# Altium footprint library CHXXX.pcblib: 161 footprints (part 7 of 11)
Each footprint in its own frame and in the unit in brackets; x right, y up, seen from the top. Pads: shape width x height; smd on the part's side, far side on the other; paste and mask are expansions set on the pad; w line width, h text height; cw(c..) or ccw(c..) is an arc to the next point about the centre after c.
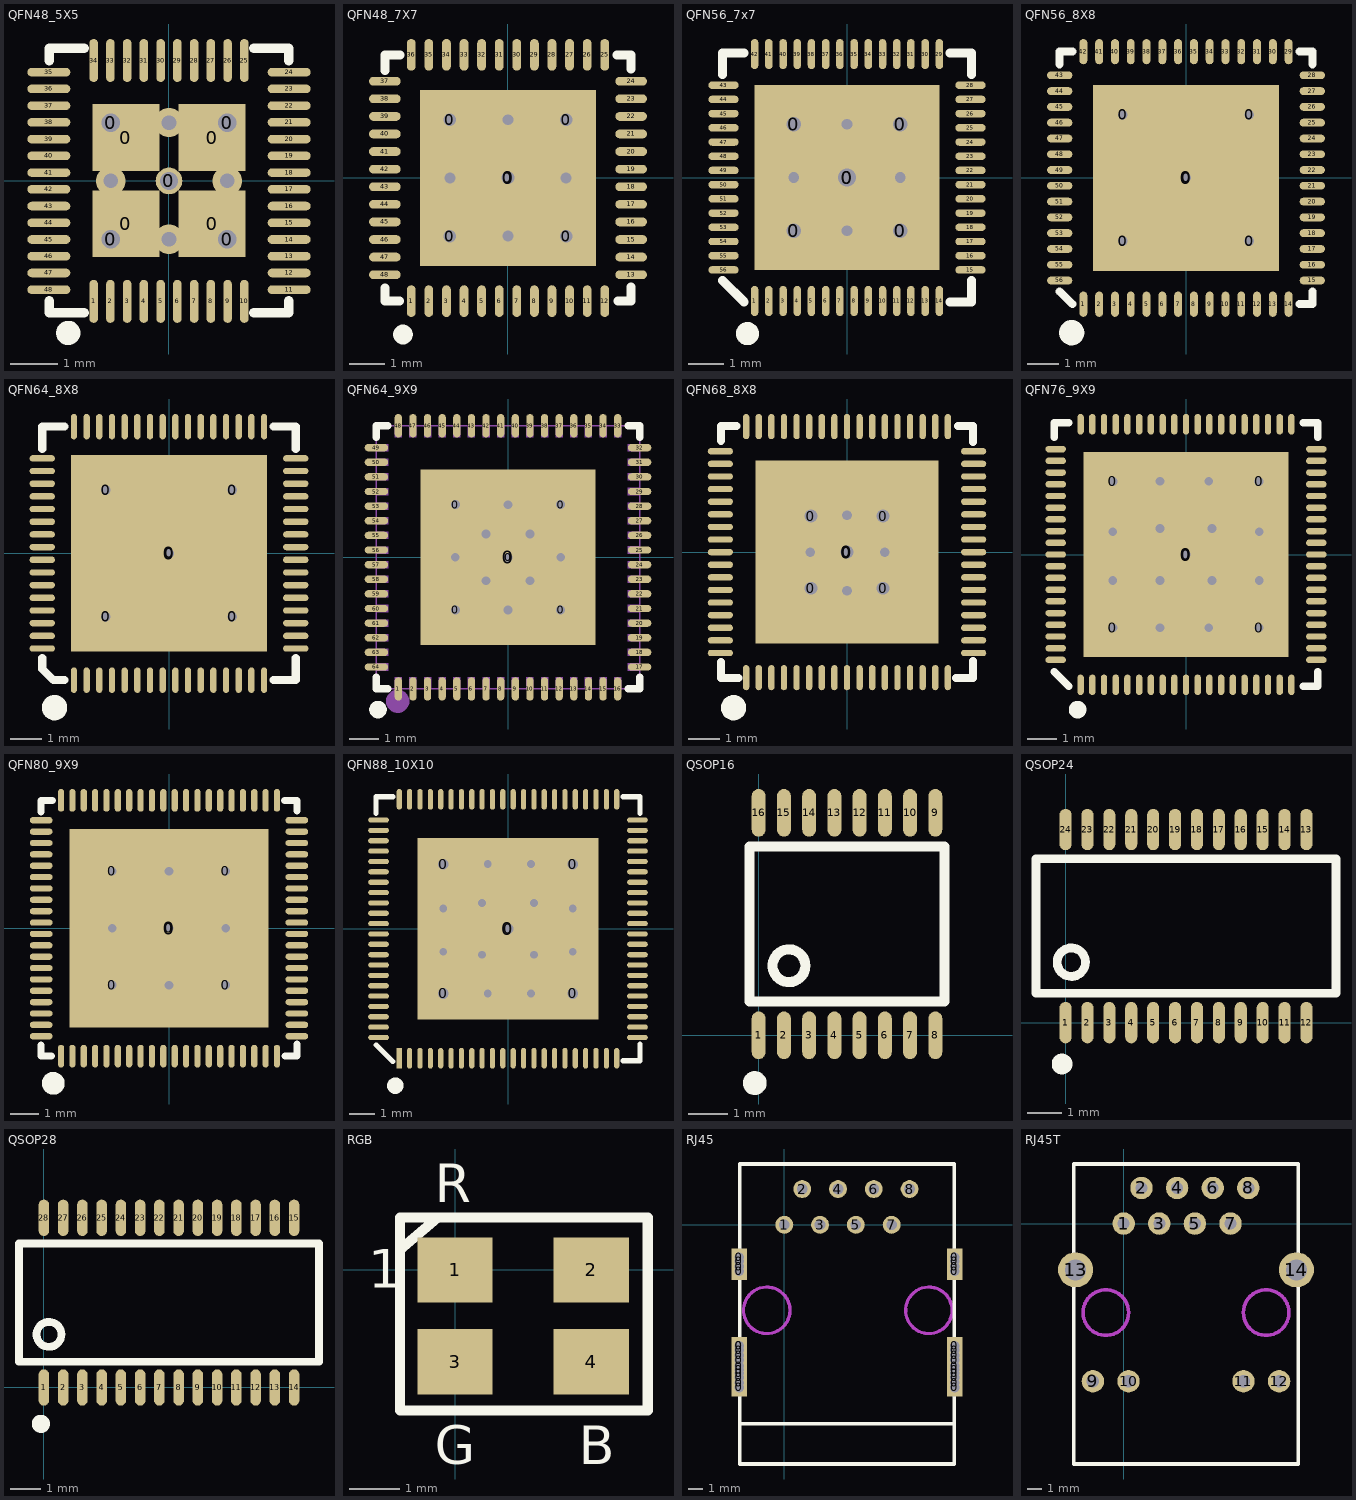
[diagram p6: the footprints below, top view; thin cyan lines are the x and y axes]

## QFN48_5X5 [mm]
pads (57):
  round 0.559 hole 0.381 mask+0.102: 0(-1.219,-1.219) 0(-1.219,1.219) 0(0,0) 0(1.219,-1.219) 0(1.219,1.219)
  rect 1.397x1.397 smd mask+0: 0(-0.901,-0.895) 0(-0.901,0.908) 0(0.902,-0.895) 0(0.902,0.908)
  oval 0.18x0.9 smd mask+0.051: 1(-1.575,-2.519) 2(-1.225,-2.519) 3(-0.875,-2.519) 4(-0.525,-2.519) 5(-0.175,-2.519) 6(0.175,-2.519) 7(0.525,-2.519) 8(0.875,-2.519) 9(1.225,-2.519) 10(1.575,-2.519) 25(1.575,2.519) 26(1.225,2.519) 27(0.875,2.519) 28(0.525,2.519) 29(0.175,2.519) 30(-0.175,2.519) 31(-0.525,2.519) 32(-0.875,2.519) 33(-1.225,2.519) 34(-1.575,2.519)
  oval 0.9x0.18 smd mask+0.051: 11(2.514,-2.275) 12(2.514,-1.925) 13(2.514,-1.575) 14(2.514,-1.225) 15(2.514,-0.875) 16(2.514,-0.525) 17(2.514,-0.175) 18(2.514,0.175) 19(2.514,0.525) 20(2.514,0.875) 21(2.514,1.225) 22(2.514,1.575) 23(2.514,1.925) 24(2.514,2.275) 35(-2.514,2.275) 36(-2.514,1.925) 37(-2.514,1.575) 38(-2.514,1.225) 39(-2.514,0.875) 40(-2.514,0.525) 41(-2.514,0.175) 42(-2.514,-0.175) 43(-2.514,-0.525) 44(-2.514,-0.875) 45(-2.514,-1.225) 46(-2.514,-1.575) 47(-2.514,-1.925) 48(-2.514,-2.275)
via 1.219,0 diameter 0.61 hole 0.305
via 0,-1.219 diameter 0.61 hole 0.305
via -1.219,0 diameter 0.61 hole 0.305
via 0,1.219 diameter 0.61 hole 0.305
TopOverlay:
  circle w0.254: c-2.108,-3.179 r0.127
  lines w0.2: -2.509,-2.506 -2.509,-2.76 -1.778,-2.76 ; -2.509,2.519 -2.509,2.772 -1.778,2.772 ; 1.778,-2.76 2.509,-2.76 2.509,-2.506 ; 1.778,2.772 2.509,2.772 2.509,2.519

## QFN48_7X7 [mm]
pads (54):
  round 0.559 hole 0.356 mask+0.102: 0(-1.651,-1.651) 0(-1.651,1.651) 0(0,0) 0(1.651,-1.651) 0(1.651,1.651)
  rect 5x5 smd mask+0.051: 0(0,0)
  oval 0.25x0.9 smd mask+0.051: 1(-2.75,-3.5) 2(-2.25,-3.5) 3(-1.75,-3.5) 4(-1.25,-3.5) 5(-0.75,-3.5) 6(-0.25,-3.5) 7(0.25,-3.5) 8(0.75,-3.5) 9(1.25,-3.5) 10(1.75,-3.5) 11(2.25,-3.5) 12(2.75,-3.5) 25(2.75,3.5) 26(2.25,3.5) 27(1.75,3.5) 28(1.25,3.5) 29(0.75,3.5) 30(0.25,3.5) 31(-0.25,3.5) 32(-0.75,3.5) 33(-1.25,3.5) 34(-1.75,3.5) 35(-2.25,3.5) 36(-2.75,3.5)
  oval 0.9x0.25 smd mask+0.051: 13(3.5,-2.75) 14(3.5,-2.25) 15(3.5,-1.75) 16(3.5,-1.25) 17(3.5,-0.75) 18(3.5,-0.25) 19(3.5,0.25) 20(3.5,0.75) 21(3.5,1.25) 22(3.5,1.75) 23(3.5,2.25) 24(3.5,2.75) 37(-3.5,2.75) 38(-3.5,2.25) 39(-3.5,1.75) 40(-3.5,1.25) 41(-3.5,0.75) 42(-3.5,0.25) 43(-3.5,-0.25) 44(-3.5,-0.75) 45(-3.5,-1.25) 46(-3.5,-1.75) 47(-3.5,-2.25) 48(-3.5,-2.75)
via -1.651,0 diameter 0.61 hole 0.305
via 0,1.651 diameter 0.61 hole 0.305
via 1.651,0 diameter 0.61 hole 0.305
via 0,-1.651 diameter 0.61 hole 0.305
TopOverlay:
  circle w0.305: c-2.986,-4.451 r0.127
  lines w0.254: -3.5,-3.128 -3.5,-3.5 -3.082,-3.5 ; -3.5,3.057 -3.5,3.5 -3.066,3.5 ; 3.099,3.5 3.5,3.5 3.5,3.096 ; 3.126,-3.5 3.5,-3.5 3.5,-3.104

## QFN56_7x7 [mm]
pads (62):
  round 0.762 hole 0.406: 0(-1.5,-1.5) 0(-1.5,1.5) 0(1.5,-1.5) 0(1.5,1.5)
  rect 5.2x5.2 smd mask+0.05: 0(0,0)
  round 0.889 hole 0.508: 0(0,0)
  oval 0.21x0.85 smd mask+0.051: 1(-2.6,-3.475) 2(-2.2,-3.475) 3(-1.8,-3.475) 4(-1.4,-3.475) 5(-1,-3.475) 6(-0.6,-3.475) 7(-0.2,-3.475) 8(0.2,-3.475) 9(0.6,-3.475) 10(1,-3.475) 11(1.4,-3.475) 12(1.8,-3.475) 13(2.2,-3.475) 14(2.6,-3.475) 29(2.6,3.475) 30(2.2,3.475) 31(1.8,3.475) 32(1.4,3.475) 33(1,3.475) 34(0.6,3.475) 35(0.2,3.475) 36(-0.2,3.475) 37(-0.6,3.475) 38(-1,3.475) 39(-1.4,3.475) 40(-1.8,3.475) 41(-2.2,3.475) 42(-2.6,3.475)
  oval 0.85x0.21 smd mask+0.051: 15(3.475,-2.6) 16(3.475,-2.2) 17(3.475,-1.8) 18(3.475,-1.4) 19(3.475,-1) 20(3.475,-0.6) 21(3.475,-0.2) 22(3.475,0.2) 23(3.475,0.6) 24(3.475,1) 25(3.475,1.4) 26(3.475,1.8) 27(3.475,2.2) 28(3.475,2.6) 43(-3.475,2.6) 44(-3.475,2.2) 45(-3.475,1.8) 46(-3.475,1.4) 47(-3.475,1) 48(-3.475,0.6) 49(-3.475,0.2) 50(-3.475,-0.2) 51(-3.475,-0.6) 52(-3.475,-1) 53(-3.475,-1.4) 54(-3.475,-1.8) 55(-3.475,-2.2) 56(-3.475,-2.6)
via -1.5,0 diameter 0.6 hole 0.3
via 0,1.5 diameter 0.6 hole 0.3
via 1.5,0 diameter 0.6 hole 0.3
via 0,-1.5 diameter 0.6 hole 0.3
TopOverlay:
  circle w0.35: c-2.803,-4.395 r0.15
  lines w0.254: -3.5,-2.899 -2.899,-3.5 ; -3.5,2.899 -3.5,3.5 -2.899,3.5 ; 2.899,-3.5 3.5,-3.5 3.5,-2.899 ; 2.899,3.5 3.5,3.5 3.5,2.899

## QFN56_8X8 [mm]
pads (62):
  round 0.61 hole 0.305 mask+0.051: 0(-2,-2) 0(-2,2) 0(0,0) 0(2,-2) 0(2,2)
  rect 5.9x5.9 smd mask+0.051: 0(0,0)
  oval 0.25x0.8 smd mask+0.051: 1(-3.25,-4) 2(-2.75,-4) 3(-2.25,-4) 4(-1.75,-4) 5(-1.25,-4) 6(-0.75,-4) 7(-0.25,-4) 8(0.25,-4) 9(0.75,-4) 10(1.25,-4) 11(1.75,-4) 12(2.25,-4) 13(2.75,-4) 14(3.25,-4) 29(3.25,4) 30(2.75,4) 31(2.25,4) 32(1.75,4) 33(1.25,4) 34(0.75,4) 35(0.25,4) 36(-0.25,4) 37(-0.75,4) 38(-1.25,4) 39(-1.75,4) 40(-2.25,4) 41(-2.75,4) 42(-3.25,4)
  oval 0.8x0.25 smd mask+0.051: 15(4,-3.25) 16(4,-2.75) 17(4,-2.25) 18(4,-1.75) 19(4,-1.25) 20(4,-0.75) 21(4,-0.25) 22(4,0.25) 23(4,0.75) 24(4,1.25) 25(4,1.75) 26(4,2.25) 27(4,2.75) 28(4,3.25) 43(-4,3.25) 44(-4,2.75) 45(-4,2.25) 46(-4,1.75) 47(-4,1.25) 48(-4,0.75) 49(-4,0.25) 50(-4,-0.25) 51(-4,-0.75) 52(-4,-1.25) 53(-4,-1.75) 54(-4,-2.25) 55(-4,-2.75) 56(-4,-3.25)
TopOverlay:
  circle w0.4: c-3.621,-4.903 r0.2
  lines w0.254: -4,-3.6 -3.6,-4 ; -4,3.6 -4,4 -3.6,4 ; 3.6,-4 4,-4 4,-3.6 ; 3.6,4 4,4 4,3.6

## QFN64_8X8 [mm]
pads (70):
  round 0.61 hole 0.305 mask+0.051: 0(-2,-2) 0(-2,2) 0(0,0) 0(2,-2) 0(2,2)
  rect 6.2x6.2 smd mask+0.051: 0(0,0)
  oval 0.2x0.8 smd mask+0.051: 1(-3,-4) 2(-2.6,-4) 3(-2.2,-4) 4(-1.8,-4) 5(-1.4,-4) 6(-1,-4) 7(-0.6,-4) 8(-0.2,-4) 9(0.2,-4) 10(0.6,-4) 11(1,-4) 12(1.4,-4) 13(1.8,-4) 14(2.2,-4) 15(2.6,-4) 16(3,-4) 33(3,4) 34(2.6,4) 35(2.2,4) 36(1.8,4) 37(1.4,4) 38(1,4) 39(0.6,4) 40(0.2,4) 41(-0.2,4) 42(-0.6,4) 43(-1,4) 44(-1.4,4) 45(-1.8,4) 46(-2.2,4) 47(-2.6,4) 48(-3,4)
  oval 0.8x0.2 smd mask+0.051: 17(4,-3) 18(4,-2.6) 19(4,-2.2) 20(4,-1.8) 21(4,-1.4) 22(4,-1) 23(4,-0.6) 24(4,-0.2) 25(4,0.2) 26(4,0.6) 27(4,1) 28(4,1.4) 29(4,1.8) 30(4,2.2) 31(4,2.6) 32(4,3) 49(-4,3) 50(-4,2.6) 51(-4,2.2) 52(-4,1.8) 53(-4,1.4) 54(-4,1) 55(-4,0.6) 56(-4,0.2) 57(-4,-0.2) 58(-4,-0.6) 59(-4,-1) 60(-4,-1.4) 61(-4,-1.8) 62(-4,-2.2) 63(-4,-2.6) 64(-4,-3)
TopOverlay:
  circle w0.4: c-3.613,-4.867 r0.2
  lines w0.254: -4,-3.3 -4,-3.65 -3.65,-4 -3.3,-4 ; -4,3.3 -4,4 -3.3,4 ; 3.3,-4 4,-4 4,-3.3 ; 3.3,4 4,4 4,3.3

## QFN64_9X9 [mm]
height 9.7
pads (70):
  round 0.508 hole 0.305 mask+0.051: 0(-1.8,-1.8) 0(-1.8,1.8) 0(0,0) 0(1.8,-1.8) 0(1.8,1.8)
  rect 6x6 smd mask+0.051: 0(0,0)
  oval 0.25x0.8 smd mask+0.051: 1(-3.75,-4.5) 2(-3.25,-4.5) 3(-2.75,-4.5) 4(-2.25,-4.5) 5(-1.75,-4.5) 6(-1.25,-4.5) 7(-0.75,-4.5) 8(-0.25,-4.5) 9(0.25,-4.5) 10(0.75,-4.5) 11(1.25,-4.5) 12(1.75,-4.5) 13(2.25,-4.5) 14(2.75,-4.5) 15(3.25,-4.5) 16(3.75,-4.5) 33(3.75,4.5) 34(3.25,4.5) 35(2.75,4.5) 36(2.25,4.5) 37(1.75,4.5) 38(1.25,4.5) 39(0.75,4.5) 40(0.25,4.5) 41(-0.25,4.5) 42(-0.75,4.5) 43(-1.25,4.5) 44(-1.75,4.5) 45(-2.25,4.5) 46(-2.75,4.5) 47(-3.25,4.5) 48(-3.75,4.5)
  oval 0.8x0.25 smd mask+0.051: 17(4.5,-3.75) 18(4.5,-3.25) 19(4.5,-2.75) 20(4.5,-2.25) 21(4.5,-1.75) 22(4.5,-1.25) 23(4.5,-0.75) 24(4.5,-0.25) 25(4.5,0.25) 26(4.5,0.75) 27(4.5,1.25) 28(4.5,1.75) 29(4.5,2.25) 30(4.5,2.75) 31(4.5,3.25) 32(4.5,3.75) 49(-4.5,3.75) 50(-4.5,3.25) 51(-4.5,2.75) 52(-4.5,2.25) 53(-4.5,1.75) 54(-4.5,1.25) 55(-4.5,0.75) 56(-4.5,0.25) 57(-4.5,-0.25) 58(-4.5,-0.75) 59(-4.5,-1.25) 60(-4.5,-1.75) 61(-4.5,-2.25) 62(-4.5,-2.75) 63(-4.5,-3.25) 64(-4.5,-3.75)
via 0,-1.8 diameter 0.6 hole 0.3
via 1.8,0 diameter 0.6 hole 0.3
via 0,1.8 diameter 0.6 hole 0.3
via -1.8,0 diameter 0.6 hole 0.3
via -0.75,-0.8 diameter 0.6 hole 0.3
via 0.75,-0.8 diameter 0.6 hole 0.3
via 0.75,0.8 diameter 0.6 hole 0.3
via -0.75,0.8 diameter 0.6 hole 0.3
TopOverlay:
  lines w0.254: -4.5,-4.106 -4.5,-4.5 -4.106,-4.5 ; -4.5,4.106 -4.5,4.5 -4.106,4.5 ; 4.106,-4.5 4.5,-4.5 4.5,-4.106 ; 4.106,4.5 4.5,4.5 4.5,4.106
  lines w0.3: -4.447,-5.057 ccw(c-4.445,-5.207) -4.443,-5.057
Mechanical6:
  circle w0.4: c-3.77,-4.92 r0.2
Mechanical15:
  drawing of 69 lines, arcs and shapes, not listed

## QFN68_8X8 [mm]
pads (74):
  round 0.559 hole 0.406: 0(-1.143,-1.143) 0(-1.143,1.143) 0(0,0) 0(1.143,-1.143) 0(1.143,1.143)
  rect 5.8x5.8 smd mask+0.051: 0(0,0)
  oval 0.2x0.8 smd mask+0.051: 1(-3.2,-3.982) 2(-2.8,-3.982) 3(-2.4,-3.982) 4(-2,-3.982) 5(-1.6,-3.982) 6(-1.2,-3.982) 7(-0.8,-3.982) 8(-0.4,-3.982) 9(0,-3.982) 10(0.4,-3.982) 11(0.8,-3.982) 12(1.2,-3.982) 13(1.6,-3.982) 14(2,-3.982) 15(2.4,-3.982) 16(2.8,-3.982) 17(3.2,-3.982) 35(3.2,3.982) 36(2.8,3.982) 37(2.4,3.982) 38(2,3.982) 39(1.6,3.982) 40(1.2,3.982) 41(0.8,3.982) 42(0.4,3.982) 43(0,3.982) 44(-0.4,3.982) 45(-0.8,3.982) 46(-1.2,3.982) 47(-1.6,3.982) 48(-2,3.982) 49(-2.4,3.982) 50(-2.8,3.982) 51(-3.2,3.982)
  oval 0.8x0.2 smd mask+0.051: 18(4.018,-3.2) 19(4.018,-2.8) 20(4.018,-2.4) 21(4.018,-2) 22(4.018,-1.6) 23(4.018,-1.2) 24(4.018,-0.8) 25(4.018,-0.4) 26(4.018,0) 27(4.018,0.4) 28(4.018,0.8) 29(4.018,1.2) 30(4.018,1.6) 31(4.018,2) 32(4.018,2.4) 33(4.018,2.8) 34(4.018,3.2) 52(-4.018,3.2) 53(-4.018,2.8) 54(-4.018,2.4) 55(-4.018,2) 56(-4.018,1.6) 57(-4.018,1.2) 58(-4.018,0.8) 59(-4.018,0.4) 60(-4.018,0) 61(-4.018,-0.4) 62(-4.018,-0.8) 63(-4.018,-1.2) 64(-4.018,-1.6) 65(-4.018,-2) 66(-4.018,-2.4) 67(-4.018,-2.8) 68(-4.018,-3.2)
via 1.194,0 diameter 0.61 hole 0.305
via 0,-1.219 diameter 0.61 hole 0.305
via -1.168,0 diameter 0.61 hole 0.305
via 0,1.168 diameter 0.61 hole 0.305
TopOverlay:
  circle w0.4: c-3.599,-4.935 r0.2
  lines w0.254: -4,-3.492 -4,-4 -3.447,-4 ; -4,3.534 -4,4 -3.503,4 ; 3.459,-4 4,-4 4,-3.458 ; 3.517,4 4,4 4,3.498

## QFN76_9X9 [mm]
pads (82):
  round 0.61 hole 0.305 mask+0.051: 0(-2.5,-2.5) 0(-2.5,2.5) 0(0,0) 0(2.5,-2.5) 0(2.5,2.5)
  rect 7x7 smd mask+0.051: 0(0,0)
  oval 0.22x0.7 smd mask+0.051: 1(-3.6,-4.45) 2(-3.2,-4.45) 3(-2.8,-4.45) 4(-2.4,-4.45) 5(-2,-4.45) 6(-1.6,-4.45) 7(-1.2,-4.45) 8(-0.8,-4.45) 9(-0.4,-4.45) 10(0,-4.45) 11(0.4,-4.45) 12(0.8,-4.45) 13(1.2,-4.45) 14(1.6,-4.45) 15(2,-4.45) 16(2.4,-4.45) 17(2.8,-4.45) 18(3.2,-4.45) 19(3.6,-4.45) 39(3.6,4.45) 40(3.2,4.45) 41(2.8,4.45) 42(2.4,4.45) 43(2,4.45) 44(1.6,4.45) 45(1.2,4.45) 46(0.8,4.45) 47(0.4,4.45) 48(0,4.45) 49(-0.4,4.45) 50(-0.8,4.45) 51(-1.2,4.45) 52(-1.6,4.45) 53(-2,4.45) 54(-2.4,4.45) 55(-2.8,4.45) 56(-3.2,4.45) 57(-3.6,4.45)
  oval 0.7x0.22 smd mask+0.051: 20(4.45,-3.6) 21(4.45,-3.2) 22(4.45,-2.8) 23(4.45,-2.4) 24(4.45,-2) 25(4.45,-1.6) 26(4.45,-1.2) 27(4.45,-0.8) 28(4.45,-0.4) 29(4.45,0) 30(4.45,0.4) 31(4.45,0.8) 32(4.45,1.2) 33(4.45,1.6) 34(4.45,2) 35(4.45,2.4) 36(4.45,2.8) 37(4.45,3.2) 38(4.45,3.6) 58(-4.45,3.6) 59(-4.45,3.2) 60(-4.45,2.8) 61(-4.45,2.4) 62(-4.45,2) 63(-4.45,1.6) 64(-4.45,1.2) 65(-4.45,0.8) 66(-4.45,0.4) 67(-4.45,0) 68(-4.45,-0.4) 69(-4.45,-0.8) 70(-4.45,-1.2) 71(-4.45,-1.6) 72(-4.45,-2) 73(-4.45,-2.4) 74(-4.45,-2.8) 75(-4.45,-3.2) 76(-4.45,-3.6)
via -0.889,0.887 diameter 0.6 hole 0.3
via -0.889,-0.887 diameter 0.6 hole 0.3
via 0.889,-0.887 diameter 0.6 hole 0.3
via 0.889,0.887 diameter 0.6 hole 0.3
via -0.889,2.5 diameter 0.6 hole 0.3
via 0.778,2.5 diameter 0.6 hole 0.3
via 2.5,0.778 diameter 0.6 hole 0.3
via 2.5,-0.889 diameter 0.6 hole 0.3
via 0.778,-2.5 diameter 0.6 hole 0.3
via -0.889,-2.5 diameter 0.6 hole 0.3
via -2.5,-0.889 diameter 0.6 hole 0.3
via -2.5,0.778 diameter 0.6 hole 0.3
TopOverlay:
  circle w0.3: c-3.704,-5.297 r0.15
  lines w0.254: -4.5,-4 -4,-4.5 ; -4.5,4 -4.5,4.5 -4,4.5 ; 4,-4.5 4.5,-4.5 4.5,-4 ; 4,4.5 4.5,4.5 4.5,4

## QFN80_9X9 [mm]
pads (86):
  round 0.61 hole 0.305 mask+0.051: 0(-2,-2) 0(-2,2) 0(0,0) 0(2,-2) 0(2,2)
  rect 7x7 smd mask+0.051: 0(0,0)
  oval 0.22x0.8 smd mask+0.051: 1(-3.8,-4.5) 2(-3.4,-4.5) 3(-3,-4.5) 4(-2.6,-4.5) 5(-2.2,-4.5) 6(-1.8,-4.5) 7(-1.4,-4.5) 8(-1,-4.5) 9(-0.6,-4.5) 10(-0.2,-4.5) 11(0.2,-4.5) 12(0.6,-4.5) 13(1,-4.5) 14(1.4,-4.5) 15(1.8,-4.5) 16(2.2,-4.5) 17(2.6,-4.5) 18(3,-4.5) 19(3.4,-4.5) 20(3.8,-4.5) 41(3.8,4.5) 42(3.4,4.5) 43(3,4.5) 44(2.6,4.5) 45(2.2,4.5) 46(1.8,4.5) 47(1.4,4.5) 48(1,4.5) 49(0.6,4.5) 50(0.2,4.5) 51(-0.2,4.5) 52(-0.6,4.5) 53(-1,4.5) 54(-1.4,4.5) 55(-1.8,4.5) 56(-2.2,4.5) 57(-2.6,4.5) 58(-3,4.5) 59(-3.4,4.5) 60(-3.8,4.5)
  oval 0.8x0.22 smd mask+0.051: 21(4.5,-3.8) 22(4.5,-3.4) 23(4.5,-3) 24(4.5,-2.6) 25(4.5,-2.2) 26(4.5,-1.8) 27(4.5,-1.4) 28(4.5,-1) 29(4.5,-0.6) 30(4.5,-0.2) 31(4.5,0.2) 32(4.5,0.6) 33(4.5,1) 34(4.5,1.4) 35(4.5,1.8) 36(4.5,2.2) 37(4.5,2.6) 38(4.5,3) 39(4.5,3.4) 40(4.5,3.8) 61(-4.5,3.8) 62(-4.5,3.4) 63(-4.5,3) 64(-4.5,2.6) 65(-4.5,2.2) 66(-4.5,1.8) 67(-4.5,1.4) 68(-4.5,1) 69(-4.5,0.6) 70(-4.5,0.2) 71(-4.5,-0.2) 72(-4.5,-0.6) 73(-4.5,-1) 74(-4.5,-1.4) 75(-4.5,-1.8) 76(-4.5,-2.2) 77(-4.5,-2.6) 78(-4.5,-3) 79(-4.5,-3.4) 80(-4.5,-3.8)
via -2,0 diameter 0.6 hole 0.3
via 0,-2 diameter 0.6 hole 0.3
via 2,0 diameter 0.6 hole 0.3
via 0,2 diameter 0.6 hole 0.3
TopOverlay:
  circle w0.4: c-4.073,-5.457 r0.2
  lines w0.254: -4.5,-4.121 -4.5,-4.5 -4.135,-4.5 ; -4.5,4.095 -4.5,4.5 -4.095,4.5 ; 4.069,4.5 4.5,4.5 4.5,4.137 ; 4.082,-4.5 4.5,-4.5 4.5,-4.079

## QFN88_10X10 [mm]
pads (94):
  round 0.711 hole 0.406 mask+0.051: 0(-2.5,-2.5) 0(-2.5,2.5) 0(0,0) 0(2.5,-2.5) 0(2.5,2.5)
  rect 7x7 smd mask+0.051: 0(0,0)
  rect 0.2x0.8 smd mask+0.051: 1(-4.2,-5)
  oval 0.2x0.8 smd mask+0.051: 2(-3.8,-5) 3(-3.4,-5) 4(-3,-5) 5(-2.6,-5) 6(-2.2,-5) 7(-1.8,-5) 8(-1.4,-5) 9(-1,-5) 10(-0.6,-5) 11(-0.2,-5) 12(0.2,-5) 13(0.6,-5) 14(1,-5) 15(1.4,-5) 16(1.8,-5) 17(2.2,-5) 18(2.6,-5) 19(3,-5) 20(3.4,-5) 21(3.8,-5) 22(4.2,-5) 45(4.2,5) 46(3.8,5) 47(3.4,5) 48(3,5) 49(2.6,5) 50(2.2,5) 51(1.8,5) 52(1.4,5) 53(1,5) 54(0.6,5) 55(0.2,5) 56(-0.2,5) 57(-0.6,5) 58(-1,5) 59(-1.4,5) 60(-1.8,5) 61(-2.2,5) 62(-2.6,5) 63(-3,5) 64(-3.4,5) 65(-3.8,5) 66(-4.2,5)
  oval 0.8x0.2 smd mask+0.051: 23(5,-4.2) 24(5,-3.8) 25(5,-3.4) 26(5,-3) 27(5,-2.6) 28(5,-2.2) 29(5,-1.8) 30(5,-1.4) 31(5,-1) 32(5,-0.6) 33(5,-0.2) 34(5,0.2) 35(5,0.6) 36(5,1) 37(5,1.4) 38(5,1.8) 39(5,2.2) 40(5,2.6) 41(5,3) 42(5,3.4) 43(5,3.8) 44(5,4.2) 67(-5,4.2) 68(-5,3.8) 69(-5,3.4) 70(-5,3) 71(-5,2.6) 72(-5,2.2) 73(-5,1.8) 74(-5,1.4) 75(-5,1) 76(-5,0.6) 77(-5,0.2) 78(-5,-0.2) 79(-5,-0.6) 80(-5,-1) 81(-5,-1.4) 82(-5,-1.8) 83(-5,-2.2) 84(-5,-2.6) 85(-5,-3) 86(-5,-3.4) 87(-5,-3.8) 88(-5,-4.2)
via 0.884,-2.5 diameter 0.6 hole 0.3
via -0.783,-2.5 diameter 0.6 hole 0.3
via -2.5,-0.884 diameter 0.6 hole 0.3
via 0.884,2.5 diameter 0.6 hole 0.3
via -2.5,0.783 diameter 0.6 hole 0.3
via 2.5,-0.884 diameter 0.6 hole 0.3
via 2.5,0.783 diameter 0.6 hole 0.3
via -0.783,2.5 diameter 0.6 hole 0.3
via -1,1 diameter 0.6 hole 0.3
via -1,-1 diameter 0.6 hole 0.3
via 1,-1 diameter 0.6 hole 0.3
via 1,1 diameter 0.6 hole 0.3
TopOverlay:
  circle w0.381: c-4.352,-6.062 r0.127
  lines w0.2: -5.1,4.45 -5.1,5.1 -4.45,5.1 ; 4.45,-5.1 5.1,-5.1 5.1,-4.45 ; 4.45,5.1 5.1,5.1 5.1,4.45
  lines w0.203: -5.089,-4.492 -4.454,-5.127

## QSOP16 [mm]
pads (16):
  oval 0.35x1.2 smd mask+0.051: 1(0,0) 2(0.635,0) 3(1.27,0) 4(1.905,0) 5(2.54,0) 6(3.175,0) 7(3.81,0) 8(4.445,0) 9(4.445,5.6) 10(3.81,5.6) 11(3.175,5.6) 12(2.54,5.6) 13(1.905,5.6) 14(1.27,5.6) 15(0.635,5.6) 16(0,5.6)
TopOverlay:
  circle w0.3: c-0.1,-1.2 r0.15
  circle w0.254: c0.762,1.752 r0.412
  lines w0.254: -0.227,0.85 -0.227,4.75 4.673,4.75 4.673,0.85 -0.227,0.85

## QSOP24 [mm]
pads (24):
  oval 0.35x1.2 smd mask+0.051: 1(0,0) 2(0.635,0) 3(1.27,0) 4(1.905,0) 5(2.54,0) 6(3.175,0) 7(3.81,0) 8(4.445,0) 9(5.08,0) 10(5.715,0) 11(6.35,0) 12(6.985,0) 13(6.985,5.6) 14(6.35,5.6) 15(5.715,5.6) 16(5.08,5.6) 17(4.445,5.6) 18(3.81,5.6) 19(3.175,5.6) 20(2.54,5.6) 21(1.905,5.6) 22(1.27,5.6) 23(0.635,5.6) 24(0,5.6)
TopOverlay:
  circle w0.3: c-0.1,-1.2 r0.15
  circle w0.254: c0.167,1.752 r0.412
  lines w0.254: -0.857,0.85 -0.857,4.75 7.843,4.75 7.843,0.85 -0.857,0.85

## QSOP28 [mm]
pads (28):
  oval 0.35x1.2 smd mask+0.051: 1(0,0) 2(0.635,0) 3(1.27,0) 4(1.905,0) 5(2.54,0) 6(3.175,0) 7(3.81,0) 8(4.445,0) 9(5.08,0) 10(5.715,0) 11(6.35,0) 12(6.985,0) 13(7.62,0) 14(8.255,0) 15(8.255,5.6) 16(7.62,5.6) 17(6.985,5.6) 18(6.35,5.6) 19(5.715,5.6) 20(5.08,5.6) 21(4.445,5.6) 22(3.81,5.6) 23(3.175,5.6) 24(2.54,5.6) 25(1.905,5.6) 26(1.27,5.6) 27(0.635,5.6) 28(0,5.6)
TopOverlay:
  circle w0.254: c0.167,1.752 r0.412
  circle w0.3: c-0.1,-1.2 r0.15
  lines w0.254: -0.823,0.85 9.078,0.85 9.078,4.75 -0.823,4.75 -0.823,0.85

## RGB [mm]
pads (4):
  rect 1.5x1.3 smd: 1(0,0) 2(2.71,0) 3(0,-1.825) 4(2.71,-1.825)
TopOverlay:
  lines w0.203: -1.09,0.404 -0.352,1.037 ; -1.092,-2.794 3.835,-2.794 3.835,1.041 -1.092,1.041 -1.092,-2.794
  text "B" at 2.464,-3.861 h0.76
  text "G" at -0.406,-3.861 h0.76
  text "R" at -0.406,1.346 h0.76
  text "1" at -1.727,-0.356 h0.76

## RJ45 [mm]
pads (37):
  rect 1.1x1.27 hole 0.701: 0(-3.2,-11.541) 0(-3.2,-11.212) 0(-3.2,-10.831) 0(-3.2,-10.541) 0(-3.2,-10.287) 0(-3.2,-10.033) 0(-3.2,-9.6) 0(-3.2,-9.271) 0(-3.2,-8.89) 0(-3.2,-8.6) 0(-3.2,-8.6) 0(-3.2,-3.3) 0(-3.2,-2.971) 0(-3.2,-2.59) 0(-3.2,-2.3) 0(12.1,-11.541) 0(12.1,-11.212) 0(12.1,-10.831) 0(12.1,-10.541) 0(12.1,-10.287) 0(12.1,-10.033) 0(12.1,-9.6) 0(12.1,-9.271) 0(12.1,-8.89) 0(12.1,-8.6) 0(12.1,-3.3) 0(12.1,-2.971) 0(12.1,-2.59) 0(12.1,-2.3)
  round 1.27 hole 0.762: 1(0,0) 2(1.27,2.54) 3(2.54,0) 4(3.81,2.54) 5(5.08,0) 6(6.35,2.54) 7(7.62,0) 8(8.89,2.54)
TopOverlay:
  lines w0.254: -3.175,-14.132 12.065,-14.132 ; 12.065,-13.335 12.065,4.318 ; 12.065,4.318 -3.175,4.318 -3.175,-16.982 12.065,-16.982 12.065,4.318
KeepOutLayer:
  circle w0.229: c10.262,-6.071 r1.651
  circle w0.229: c-1.245,-6.071 r1.651
Mechanical1:
  circle w0.229: c10.262,-6.071 r1.651
  circle w0.229: c-1.245,-6.071 r1.651

## RJ45T [mm]
pads (14):
  round 1.6 hole 0.85: 1(0,0) 2(1.27,2.54) 3(2.54,0) 4(3.81,2.54) 5(5.08,0) 6(6.35,2.54) 7(7.62,0) 8(8.89,2.54)
  round 1.6 hole 0.9: 9(-2.195,-11.25) 10(0.345,-11.25) 11(8.545,-11.25) 12(11.085,-11.25)
  round 2.5 hole 1.5: 13(-3.43,-3.3) 14(12.32,-3.3)
TopOverlay:
  lines w0.254: -3.555,-17.15 12.445,-17.15 12.445,4.25 -3.555,4.25 -3.555,-17.15
KeepOutLayer:
  circle w0.254: c-1.27,-6.35 r1.625
  circle w0.254: c10.16,-6.35 r1.625
Mechanical1:
  circle w0.254: c-1.27,-6.35 r1.625
  circle w0.254: c10.16,-6.35 r1.625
